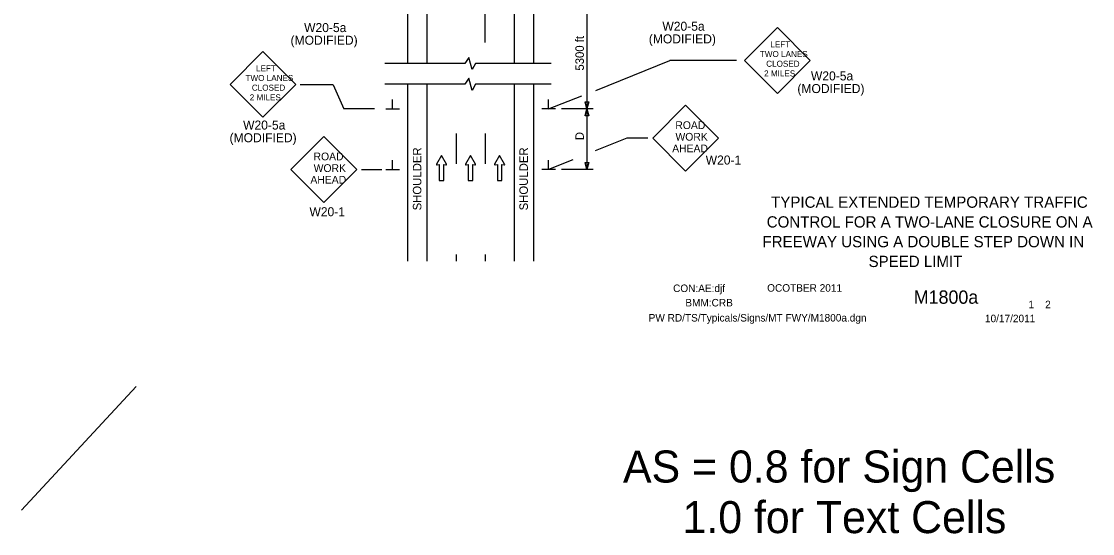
# Model space of a CAD drawing. Extents: x 16553 to 18478, y 5759 to 7026.
# Drawn here: x 16553 to 17437, y 5759 to 6181 of the extents above; entities that cross this region are included whole.
import ezdxf

# ---------------------------------------------------------------- set-up
doc = ezdxf.new("R2010")
doc.units = 0
for name, color, linetype in [('ALI_LEGAL_EX', 7, 'Continuous'), ('BORDER', 7, 'Continuous'), ('BORDER_SIGNAL_WO', 7, 'Continuous'), ('MT_SCRATCH_LEVEL_E', 7, 'Continuous'), ('PAVT_EDGE_EX', 7, 'Continuous'), ('TRAFFIC_SIGNS_PR', 7, 'Continuous'), ('TYPICAL_TEXT_DIMEN_PR', 7, 'Continuous')]:
    doc.layers.add(name, color=color, linetype=linetype)

msp = doc.modelspace()

# ---------------------------------------------------------------- linework, layer by layer
at = {"layer": 'ALI_LEGAL_EX'}
for points in [[(16935.66, 6163.99), (16935.66, 6188.99)], [(16911.66, 6088.99), (16911.66, 6063.99)], [(16935.66, 6088.99), (16935.66, 6063.99)], [(16911.66, 5988.99), (16911.66, 5983.43)], [(16935.66, 5988.99), (16935.66, 5983.43)]]:
    msp.add_lwpolyline(points, dxfattribs=at)
at = {"layer": 'MT_SCRATCH_LEVEL_E'}
for p, q in [((16899.66, 6070.89), (16895.55, 6063.65)), ((16903.81, 6063.65), (16899.66, 6070.89)), ((16923.57, 6070.89), (16919.46, 6063.65)), ((16927.71, 6063.65), (16923.57, 6070.89)), ((16947.62, 6070.89), (16943.51, 6063.65)), ((16951.77, 6063.65), (16947.62, 6070.89)), ((16896.03, 6062.97), (16897.81, 6063.28)), ((16897.81, 6063.28), (16897.81, 6050.03)), ((16901.55, 6050.03), (16901.55, 6063.28)), ((16901.55, 6063.28), (16903.33, 6062.97)), ((16919.94, 6062.97), (16921.72, 6063.28)), ((16921.72, 6063.28), (16921.72, 6050.03)), ((16925.46, 6050.03), (16925.46, 6063.28)), ((16925.46, 6063.28), (16927.24, 6062.97)), ((16943.99, 6062.97), (16945.77, 6063.28)), ((16945.77, 6063.28), (16945.77, 6050.03)), ((16949.51, 6050.03), (16949.51, 6063.28)), ((16949.51, 6063.28), (16951.29, 6062.97)), ((16897.81, 6050.03), (16901.55, 6050.03)), ((16921.72, 6050.03), (16925.46, 6050.03)), ((16945.77, 6050.03), (16949.51, 6050.03))]:
    msp.add_line(p, q, dxfattribs=at)
for centre, start, end in [((16895.96, 6063.43), 150.42484, 279.96381), ((16903.4, 6063.43), 260.03619, 29.77312), ((16919.86, 6063.43), 150.42484, 279.96381), ((16927.3, 6063.43), 260.03619, 29.77312), ((16943.92, 6063.43), 150.42484, 279.96381), ((16951.36, 6063.43), 260.03619, 29.77312)]:
    msp.add_arc(centre, 0.463, start, end, dxfattribs=at)
at = {"layer": 'PAVT_EDGE_EX'}
for p, q in [((16871.66, 6223.96), (16871.66, 6146.79)), ((16887.66, 6223.96), (16887.66, 6146.8)), ((16959.66, 6223.96), (16959.66, 6146.8)), ((16975.66, 6223.96), (16975.66, 6146.8)), ((16871.66, 6129.66), (16871.66, 5983.43)), ((16887.66, 6129.66), (16887.66, 5983.43)), ((16959.66, 6129.66), (16959.66, 5983.43)), ((16975.66, 6129.66), (16975.66, 5983.43))]:
    msp.add_line(p, q, dxfattribs=at)
at = {"layer": 'TRAFFIC_SIGNS_PR'}
for p, q in [((17176.68, 6176.39), (17149.49, 6149.2)), ((17203.87, 6149.2), (17176.68, 6176.39)), ((16752.46, 6156.65), (16725.27, 6129.46)), ((16779.65, 6129.46), (16752.46, 6156.65)), ((17149.49, 6149.2), (17176.68, 6122.02)), ((17176.68, 6122.02), (17203.87, 6149.2)), ((16725.27, 6129.46), (16752.46, 6102.27)), ((16752.46, 6102.27), (16779.65, 6129.46)), ((17101.01, 6112.22), (17073.86, 6085.06)), ((17128.16, 6085.06), (17101.01, 6112.22)), ((16802.6, 6086.36), (16775.44, 6059.21)), ((16829.75, 6059.21), (16802.6, 6086.36)), ((17073.86, 6085.06), (17101.01, 6057.91)), ((17101.01, 6057.91), (17128.16, 6085.06)), ((16775.44, 6059.21), (16802.6, 6032.06)), ((16802.6, 6032.06), (16829.75, 6059.21))]:
    msp.add_line(p, q, dxfattribs=at)
at = {"layer": 'TYPICAL_TEXT_DIMEN_PR'}
for p, q in [((17019.66, 6209.23), (17019.66, 6109.23)), ((16922.27, 6151.59), (16919.01, 6146.79)), ((16925.01, 6141.65), (16922.27, 6151.59)), ((17027.05, 6124.46), (17088.12, 6149.1)), ((17143.12, 6149.1), (17088.12, 6149.1)), ((16919.01, 6146.79), (16853.07, 6146.79)), ((16927.75, 6146.79), (16925.01, 6141.65)), ((16990.08, 6146.79), (16927.75, 6146.79)), ((16922.27, 6134.45), (16919.01, 6129.65)), ((16925.01, 6124.51), (16922.27, 6134.45)), ((16810.37, 6129.13), (16783.2, 6129.13)), ((16810.37, 6129.13), (16819.13, 6109.23)), ((16919.01, 6129.65), (16853.07, 6129.65)), ((16927.75, 6129.65), (16925.01, 6124.51)), ((16990.08, 6129.65), (16927.75, 6129.65)), ((16859.29, 6109.23), (16859.29, 6117.01)), ((16988.04, 6109.22), (17015.3, 6119.87)), ((16988.04, 6109.23), (16988.04, 6117.01)), ((17019.66, 6109.23), (17018.09, 6115.09)), ((17018.09, 6115.09), (17019.66, 6115.09)), ((17019.66, 6115.09), (17021.24, 6115.09)), ((17021.24, 6115.09), (17019.66, 6109.23)), ((16844.35, 6109.23), (16819.13, 6109.23)), ((16853.66, 6109.23), (16864.91, 6109.23)), ((16993.66, 6109.23), (16982.41, 6109.23)), ((17024.66, 6109.23), (16998.66, 6109.23)), ((17018.09, 6103.36), (17019.66, 6109.23)), ((17019.66, 6109.23), (17019.66, 6059.23)), ((17019.66, 6109.23), (17021.24, 6103.36)), ((17019.66, 6103.36), (17018.09, 6103.36)), ((17021.24, 6103.36), (17019.66, 6103.36)), ((17052.49, 6085.03), (17026.51, 6074.62)), ((17069.75, 6085.03), (17052.49, 6085.03)), ((16859.29, 6059.23), (16859.29, 6067.01)), ((17008.08, 6067.25), (16988.04, 6059.22)), ((16988.04, 6059.23), (16988.04, 6067.01)), ((17019.66, 6059.23), (17018.09, 6065.09)), ((17018.09, 6065.09), (17019.66, 6065.09)), ((17019.66, 6065.09), (17021.24, 6065.09)), ((17021.24, 6065.09), (17019.66, 6059.23)), ((16833.74, 6059.23), (16850.58, 6059.23)), ((16853.66, 6059.23), (16864.91, 6059.23)), ((16993.66, 6059.23), (16982.41, 6059.23)), ((17024.66, 6059.23), (16998.66, 6059.23)), ((16647.75, 5880), (16553.21, 5777.94))]:
    msp.add_line(p, q, dxfattribs=at)

# ---------------------------------------------------------------- texts
at = {"layer": 'BORDER'}
for s, p in [('TYPICAL EXTENDED TEMPORARY TRAFFIC', (17171.54, 6027.6)), ('CONTROL FOR A TWO-LANE CLOSURE ON A', (17167.92, 6011.3)), ('FREEWAY USING A DOUBLE STEP DOWN IN ', (17164.42, 5995)), ('SPEED LIMIT', (17251.92, 5978.7))]:
    msp.add_text(s, height=9.3, dxfattribs=at).set_placement(p)
at = {"layer": 'BORDER_SIGNAL_WO'}
for s, height, p in [('CON:AE:djf  ', 6.2, (17090.69, 5958.06)), ('    OCOTBER 2011', 6.2, (17159.08, 5958.34)), ('    M1800a   ', 11, (17272.86, 5948.38)), ('BMM:CRB', 6.2, (17100.81, 5946.17)), (' 1    2 ', 6.2, (17381.45, 5944.7)), ('PW RD/TS/Typicals/Signs/MT FWY/M1800a.dgn      ', 6.2, (17070.55, 5933.71)), ('10/17/2011', 6.2, (17347.93, 5933.13)), ('AS = 0.8 for Sign Cells', 26.4241, (17049.39, 5800.83)), ('     1.0 for Text Cells', 26.4241, (17049.39, 5759.05))]:
    msp.add_text(s, height=height, dxfattribs=at).set_placement(p)
at = {"layer": 'TRAFFIC_SIGNS_PR'}
for s, height, p in [('W20-5a', 7.449, (16786.36, 6172.62)), ('W20-5a', 7.449, (17081.85, 6173.73)), ('(MODIFIED)', 7.449, (16775.2, 6162.17)), ('(MODIFIED)', 7.449, (17070.69, 6163.28)), ('LEFT', 5.006, (17170.92, 6160)), ('TWO LANES', 5.006, (17162.27, 6151.99)), ('CLOSED', 5.006, (17167.51, 6143.98)), ('LEFT', 5.006, (16746.7, 6140.26)), ('2 MILES', 5.006, (17165.75, 6135.98)), ('W20-5a', 7.449, (17204.37, 6132.73)), ('TWO LANES', 5.006, (16738.05, 6132.25)), ('CLOSED', 5.006, (16743.28, 6124.24)), ('(MODIFIED)', 7.449, (17193.21, 6122.28)), ('2 MILES', 5.006, (16741.53, 6116.23)), ('W20-5a', 7.449, (16736.04, 6092.15)), ('ROAD', 6.4, (17092.55, 6092.6)), ('(MODIFIED)', 7.449, (16724.88, 6081.7)), ('WORK', 6.4, (17092.66, 6083)), ('AHEAD', 6.4, (17089.97, 6073.4)), ('ROAD', 6.4, (16794.14, 6066.75)), ('W20-1', 7.44, (17117.59, 6063.3)), ('WORK', 6.4, (16794.25, 6057.15)), ('AHEAD', 6.4, (16791.56, 6047.55)), ('W20-1', 7.44, (16790.77, 6020.62))]:
    msp.add_text(s, height=height, dxfattribs=at).set_placement(p)
at = {"layer": 'TYPICAL_TEXT_DIMEN_PR'}
for s, p in [('5300 ft', (17017.11, 6140.83)), ('D', (17017.11, 6083.44)), ('SHOULDER', (16883.08, 6025.44)), ('SHOULDER', (16970.94, 6025.44))]:
    msp.add_text(s, height=7, rotation=90, dxfattribs=at).set_placement(p)

doc.saveas('drawing.dxf')
